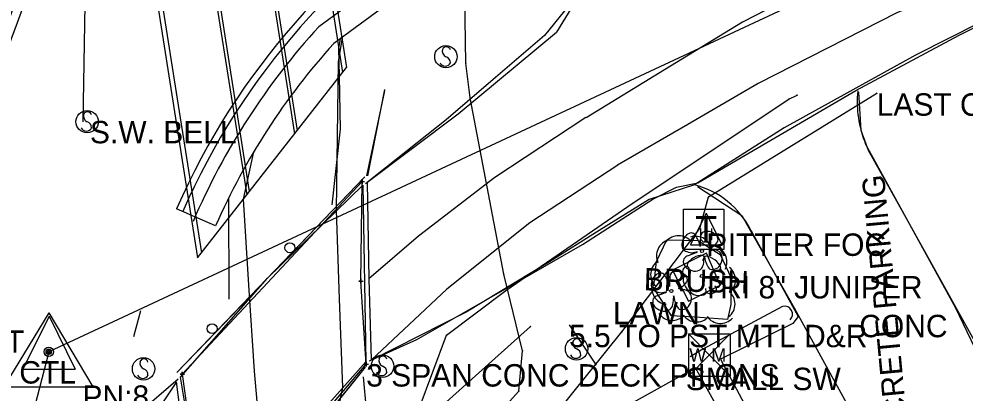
# Model space of a CAD drawing. Extents: x 978516 to 993312, y 1836504 to 1846212.
# Drawn here: x 992686.2 to 992897.2, y 1840515.9 to 1840599.3 of the extents above; entities that cross this region are included whole.
import ezdxf

# ---------------------------------------------------------------- set-up
doc = ezdxf.new("R2010")
doc.units = 0
for name, color, linetype in [('R_Drainage', 7, 'Continuous'), ('R_MOT Stage 1 Widening', 7, 'Continuous'), ('R_Proposed Road', 7, 'Continuous'), ('S_BASELINE', 7, 'Continuous'), ('S_BRIDGE', 7, 'Continuous'), ('S_BRIDGE_ANNOT', 7, 'Continuous'), ('S_BUILDING', 7, 'Continuous'), ('S_CAL_CORNER', 7, 'Continuous'), ('S_DRIVEWAY', 7, 'Continuous'), ('S_EDGE_PAVEMENT', 7, 'Continuous'), ('S_FENCE', 7, 'Continuous'), ('S_FIBER_OPTIC_CABLE', 7, 'Continuous'), ('S_FIBER_OPTIC_CABLE_ANNOT', 7, 'Continuous'), ('S_GAS_UTILITIES', 7, 'Continuous'), ('S_GUARDRAIL', 7, 'Continuous'), ('S_HEADWALL', 7, 'Continuous'), ('S_PARKING', 7, 'Continuous'), ('S_PARKING_ANNOT', 7, 'Continuous'), ('S_PAVEMENT_CROWN', 7, 'Continuous'), ('S_PRIMARY_CTL', 7, 'Continuous'), ('S_PRIMARY_CTL_ANNOT', 7, 'Continuous'), ('S_SHOULDER', 7, 'Continuous'), ('S_SIDEWALK', 7, 'Continuous'), ('S_SIGN', 7, 'Continuous'), ('S_SIGN_ANNOT', 7, 'Continuous'), ('S_STR_PT_SYM', 7, 'Continuous'), ('S_STREAM', 7, 'Continuous'), ('S_SURVEY_TEXT_ANNOT', 7, 'Continuous'), ('S_TELEPHONE_UTILITIES', 7, 'Continuous'), ('S_TREE', 7, 'Continuous'), ('S_TREE_ANNOT', 7, 'Continuous'), ('S_UNDERGROUND_CABLE', 7, 'Continuous'), ('S_UTILITY_POLE_ANNOT', 7, 'Continuous'), ('S_UTL_PT_SYM', 7, 'Continuous'), ('S_WALL', 7, 'Continuous'), ('S_WATER_UTILITIES', 7, 'Continuous')]:
    doc.layers.add(name, color=color, linetype=linetype)

msp = doc.modelspace()

# ---------------------------------------------------------------- linework, layer by layer
at = {"layer": 'R_Drainage'}
for p, q in [((992722.23, 1840823.99), (992759.26, 1840588.45)), ((992721.57, 1840821.45), (992758.38, 1840587.32)), ((992711.58, 1840807.74), (992748.27, 1840574.41)), ((992711.02, 1840806.97), (992747.7, 1840573.69)), ((992701.03, 1840793.26), (992737.59, 1840560.77)), ((992700.48, 1840792.49), (992737.03, 1840560.05)), ((992689.24, 1840780.01), (992726.03, 1840546.01)), ((992690.27, 1840780.17), (992726.91, 1840547.13)), ((992726.03, 1840546.01), (992759.26, 1840588.45))]:
    msp.add_line(p, q, dxfattribs=at)
at = {"layer": 'R_MOT Stage 1 Widening'}
for radius in [585.96, 583.96]:
    msp.add_arc((993234.41, 1840398.18), radius, 157.55254, 164.93538, dxfattribs=at)
at = {"layer": 'R_Proposed Road'}
for p, q in [((992802.25, 1840633.66), (992753.09, 1840597.56)), ((992804.81, 1840629.34), (992756.46, 1840593.83)), ((992730.1, 1840553.16), (992721.4, 1840556.97)), ((992711.86, 1840528.47), (992713.43, 1840534.3))]:
    msp.add_line(p, q, dxfattribs=at)
for radius, start, end in [(160, 86.363, 156.3203), (158.5, 86.363, 156.3203), (155.5, 137.6025, 156.741), (150.5, 137.7895, 156.3203)]:
    msp.add_arc((992867.93, 1840492.71), radius, start, end, dxfattribs=at)
at = {"layer": 'S_BASELINE'}
for p, q in [((993084.19, 1840707.66), (992692.91, 1840525.06)), ((992692.91, 1840525.06), (992469.46, 1839669.75))]:
    msp.add_line(p, q, dxfattribs=at)
at = {"layer": 'S_BRIDGE'}
for p, q in [((992762.75, 1840563.05), (992722.66, 1840520.07)), ((992762.5, 1840540.83), (992762.75, 1840563.05)), ((992763.66, 1840522.31), (992762.5, 1840540.83)), ((992727.57, 1840479.81), (992763.66, 1840522.31)), ((992722.66, 1840520.07), (992725.42, 1840500.17))]:
    msp.add_line(p, q, dxfattribs=at)
msp.add_lwpolyline([(992741.67, 1840541.48), (992762.9, 1840562.2), (992763.6, 1840522.8), (992746.71, 1840503.81), (992728.74, 1840480.59), (992722.25, 1840519.42)], close=True, dxfattribs=at)
at = {"layer": 'S_BUILDING'}
msp.add_lwpolyline([(992808.57, 1840505.65), (992829.2, 1840468.57), (992857.68, 1840484.4), (992837.04, 1840521.49)], close=True, dxfattribs=at)
at = {"layer": 'S_CAL_CORNER'}
for p, q in [((992693, 1840533.04), (992687.12, 1840521.22)), ((992693, 1840533.04), (992698.81, 1840521.22)), ((992687.12, 1840521.22), (992698.81, 1840521.22))]:
    msp.add_line(p, q, dxfattribs=at)
at = {"layer": 'S_DRIVEWAY'}
for points in [[(992906.73, 1840514.11), (992898.92, 1840528.17), (992891.11, 1840542.23), (992883.37, 1840556.1), (992875.63, 1840569.96), (992874.01, 1840574.41), (992873.47, 1840582.95)], [(992837.52, 1840561.93), (992847.36, 1840555.43), (992859.05, 1840534.9), (992865.85, 1840522.52), (992872.66, 1840510.14), (992879.81, 1840497.28)]]:
    msp.add_lwpolyline(points, dxfattribs=at)
at = {"layer": 'S_EDGE_PAVEMENT'}
for points in [[(993177.91, 1840647.47), (993161.87, 1840647.02), (993145.83, 1840646.57), (993129.79, 1840646.12), (993113.75, 1840645.67), (993089.5, 1840644.32), (993065.25, 1840642.97), (993051.93, 1840641.71), (993038.62, 1840640.45), (993025.3, 1840639.2), (993011.99, 1840637.94), (992997.08, 1840635.43), (992982.18, 1840632.93), (992964.68, 1840629), (992947.18, 1840625.07), (992929.74, 1840619.35), (992912.31, 1840613.64), (992897.13, 1840607.12), (992881.95, 1840600.61), (992866.5, 1840592.73), (992851.05, 1840584.86), (992835.38, 1840575.78), (992819.71, 1840566.7)], [(992816.12, 1840634.02), (992817.57, 1840628.43), (992818.03, 1840619.07), (992813.29, 1840609.04), (992807.87, 1840601.1), (992803.43, 1840595.57), (992792.47, 1840586.2), (992781.52, 1840576.82), (992763.89, 1840562.82), (992764.24, 1840541.31), (992764.8, 1840523.27)], [(992814.31, 1840609.86), (992806.06, 1840596.37)], [(992819.73, 1840566.69), (992800.1, 1840553.83), (992781.65, 1840539), (992764.81, 1840523.24)], [(992727.17, 1840479.58), (992723.79, 1840499.26), (992721.4, 1840518.33), (992709.95, 1840501.18), (992698.5, 1840484.04), (992688.92, 1840468.82), (992679.35, 1840453.6), (992673.45, 1840441.41), (992667.56, 1840429.21), (992661.66, 1840417.01)]]:
    msp.add_lwpolyline(points, dxfattribs=at)
at = {"layer": 'S_FENCE'}
msp.add_lwpolyline([(992690.72, 1840637.87), (992701.52, 1840637.54), (992700.49, 1840576.34)], dxfattribs=at)
at = {"layer": 'S_FIBER_OPTIC_CABLE'}
for p, q in [((992785.88, 1840589.39), (992784.86, 1840660.38)), ((992786.81, 1840581.67), (992785.88, 1840589.39)), ((992839.93, 1840559.6), (992877.46, 1840582.7)), ((992794.32, 1840542.4), (992786.81, 1840581.67)), ((992838.05, 1840552.56), (992839.93, 1840559.6)), ((992820.65, 1840529.49), (992838.05, 1840552.56)), ((992798.51, 1840525.29), (992794.32, 1840542.4)), ((992788.25, 1840489.33), (992820.65, 1840529.49)), ((992797.72, 1840516.31), (992798.51, 1840525.29)), ((992781.05, 1840497.97), (992797.72, 1840516.31))]:
    msp.add_line(p, q, dxfattribs=at)
at = {"layer": 'S_GAS_UTILITIES'}
for p, q in [((992857.87, 1840581.4), (992859.74, 1840582.32)), ((992823.2, 1840558.29), (992857.87, 1840581.4)), ((992794.82, 1840538.73), (992823.2, 1840558.29)), ((992781.54, 1840528.78), (992794.82, 1840538.73)), ((992780.08, 1840512.54), (992800.28, 1840530.72)), ((992775.47, 1840512.42), (992781.54, 1840528.78))]:
    msp.add_line(p, q, dxfattribs=at)
at = {"layer": 'S_GUARDRAIL'}
for points in [[(992721.45, 1840520.43), (992763.34, 1840564.05)], [(992756.09, 1840556.5), (992763.34, 1840564.05)], [(992747.43, 1840547.48), (992756.09, 1840556.5)], [(992730.11, 1840529.45), (992747.43, 1840547.48)], [(992721.45, 1840520.43), (992730.11, 1840529.45)], [(992763.45, 1840521.65), (992727.06, 1840476.56)], [(992763.45, 1840521.65), (992755.6, 1840511.92)]]:
    msp.add_lwpolyline(points, dxfattribs=at)
for centre in [(992746.64, 1840548.25), (992729.32, 1840530.21)]:
    msp.add_circle(centre, 1.1, dxfattribs=at)
at = {"layer": 'S_HEADWALL'}
for points in [[(992767.77, 1840583.55), (992763.94, 1840564.3)], [(992763, 1840519.48), (992763.68, 1840512.17)]]:
    msp.add_lwpolyline(points, dxfattribs=at)
at = {"layer": 'S_PARKING'}
for points in [[(992874.99, 1840571.38), (992895.05, 1840534.87), (992906.92, 1840510.07)], [(992849.37, 1840552.22), (992859.98, 1840532.9), (992858.79, 1840531.37), (992842.62, 1840523.39), (992861.57, 1840487.89), (992878.33, 1840497.58)]]:
    msp.add_lwpolyline(points, dxfattribs=at)
msp.add_arc((992898.2, 1840580.9), 25.09, 174.5543, 202.3004, dxfattribs=at)
msp.add_ellipse((992831.99, 1840543.4), major_axis=(5.73, 18.65), ratio=0.998187, start_param=5.479068, end_param=6.328259, dxfattribs=at)
at = {"layer": 'S_PAVEMENT_CROWN'}
for points in [[(992907.52, 1840626.08), (992890.94, 1840619.3), (992874.36, 1840612.52), (992860.96, 1840605.55), (992847.56, 1840598.59), (992830.13, 1840587.9), (992812.7, 1840577.21)], [(992812.6, 1840577.29), (992792.33, 1840563.91), (992775.35, 1840550.83), (992764.23, 1840541.36)]]:
    msp.add_lwpolyline(points, dxfattribs=at)
at = {"layer": 'S_PRIMARY_CTL'}
for p, q in [((992692.91, 1840533.76), (992682.88, 1840517.25)), ((992692.91, 1840533.76), (992702.74, 1840517.25)), ((992682.88, 1840517.25), (992702.74, 1840517.25))]:
    msp.add_line(p, q, dxfattribs=at)
for radius in [1.04, 0.609, 0.344]:
    msp.add_circle((992692.91, 1840525.06), radius, dxfattribs=at)
at = {"layer": 'S_SHOULDER'}
for points in [[(992764.42, 1840523.04), (992774.98, 1840527.84), (992792.1, 1840537.6), (992811.9, 1840549), (992827.56, 1840559.12), (992832.85, 1840561.75), (992837.56, 1840562.73), (992872.77, 1840583.33), (992895.85, 1840595.64), (992918.17, 1840606.95), (992952.31, 1840617.76), (992986.76, 1840625.23), (993023.98, 1840630.67)], [(992900.35, 1840598.41), (992886.07, 1840591.18), (992871.44, 1840583.1), (992856.81, 1840575.03), (992836.84, 1840562.32), (992826.74, 1840559.04), (992815.62, 1840552.1), (992804.51, 1840545.15), (992785.95, 1840533.87), (992764.82, 1840523.23)], [(992763.48, 1840562.59), (992784.18, 1840578.13), (992806.06, 1840596.37)], [(992679.93, 1840469.45), (992694.86, 1840491.14), (992712.59, 1840511.13), (992721.74, 1840519.04)]]:
    msp.add_lwpolyline(points, dxfattribs=at)
at = {"layer": 'S_SIDEWALK'}
msp.add_lwpolyline([(992856.48, 1840535.18), (992838.73, 1840525.65), (992835.85, 1840523.95)], dxfattribs=at)
msp.add_arc((992856.92, 1840533.45), 1.78, 313.4272, 104.1775, dxfattribs=at)
at = {"layer": 'S_SIGN'}
msp.add_line((992808.88, 1840531.09), (992814.94, 1840522.06), dxfattribs=at)
for centre in [(992781.43, 1840590.87), (992701.45, 1840576.37), (992810.54, 1840525.71), (992714.03, 1840521.25), (992767.3, 1840521.85)]:
    msp.add_circle(centre, 2.49, dxfattribs=at)
for centre, radius, start, end in [((992782.12, 1840592.19), 1.5, 167.1196, 241.9813), ((992781.51, 1840592.13), 0.95, 16.5258, 156.8957), ((992781.02, 1840589.52), 1.4, 358.6529, 73.7063), ((992781.28, 1840590.04), 1.28, 204.641, 335.359), ((992702.13, 1840577.69), 1.5, 167.1196, 241.9813), ((992701.52, 1840577.64), 0.95, 16.5258, 156.8957), ((992701.04, 1840575.03), 1.4, 358.6529, 73.7063), ((992701.29, 1840575.55), 1.28, 204.641, 335.359), ((992811.22, 1840527.04), 1.5, 167.1196, 241.9813), ((992810.61, 1840526.98), 0.95, 16.5258, 156.8957), ((992810.13, 1840524.37), 1.4, 358.6529, 73.7063), ((992714.72, 1840522.57), 1.5, 167.1196, 241.9813), ((992714.11, 1840522.51), 0.95, 16.5258, 156.8957), ((992767.98, 1840523.18), 1.5, 167.1196, 241.9813), ((992767.37, 1840523.12), 0.95, 16.5258, 156.8957), ((992810.38, 1840524.89), 1.28, 204.641, 335.359), ((992713.62, 1840519.9), 1.4, 358.6529, 73.7063), ((992766.88, 1840520.51), 1.4, 358.6529, 73.7063), ((992713.88, 1840520.42), 1.28, 204.641, 335.359), ((992767.14, 1840521.03), 1.28, 204.641, 335.359)]:
    msp.add_arc(centre, radius, start, end, dxfattribs=at)
at = {"layer": 'S_STR_PT_SYM'}
for points in [[(992762.75, 1840563.05), (992762.75, 1840563.55), (992762.75, 1840563.05), (992762.25, 1840563.05), (992762.75, 1840563.05), (992762.75, 1840562.55), (992762.75, 1840563.05), (992763.25, 1840563.05)], [(992762.5, 1840540.83), (992762.5, 1840541.33), (992762.5, 1840540.83), (992762, 1840540.83), (992762.5, 1840540.83), (992762.5, 1840540.33), (992762.5, 1840540.83), (992763, 1840540.83)], [(992763.66, 1840522.31), (992763.66, 1840522.81), (992763.66, 1840522.31), (992763.16, 1840522.31), (992763.66, 1840522.31), (992763.66, 1840521.81), (992763.66, 1840522.31), (992764.16, 1840522.31)], [(992722.66, 1840520.07), (992722.66, 1840520.57), (992722.66, 1840520.07), (992722.16, 1840520.07), (992722.66, 1840520.07), (992722.66, 1840519.57), (992722.66, 1840520.07), (992723.16, 1840520.07)]]:
    msp.add_lwpolyline(points, dxfattribs=at)
at = {"layer": 'S_STREAM'}
for points in [[(992758.28, 1840595.17), (992757.44, 1840589.73), (992757.19, 1840573.18), (992756.93, 1840556.62), (992757.65, 1840536.86), (992758.37, 1840517.1), (992755.48, 1840503.1), (992752.59, 1840489.1), (992750.17, 1840482.23), (992751.22, 1840469.43), (992752.27, 1840456.64), (992752.39, 1840435.4), (992746.88, 1840418.83), (992741.38, 1840402.27), (992735.04, 1840383.73), (992728.7, 1840365.18)], [(992757.89, 1840594.88), (992757.49, 1840592.74), (992757.65, 1840586.53), (992757.87, 1840574.71), (992755.97, 1840557.84)], [(992738.56, 1840569.62), (992736.23, 1840559.11), (992737.44, 1840539.91), (992738.66, 1840520.72), (992739.87, 1840507.19), (992741.09, 1840493.67), (992741.97, 1840482.66), (992743.33, 1840457.87), (992744.81, 1840435.72), (992739.02, 1840420.42), (992733.23, 1840405.13), (992725.57, 1840391.67), (992717.91, 1840378.21)], [(992733.08, 1840536.77), (992733.01, 1840559.39)]]:
    msp.add_lwpolyline(points, dxfattribs=at)
at = {"layer": 'S_TELEPHONE_UTILITIES'}
msp.add_lwpolyline([(992834.41, 1840547.87), (992834.41, 1840556.87), (992843.41, 1840556.87), (992843.41, 1840547.87)], close=True, dxfattribs=at)
at = {"layer": 'S_TREE'}
for p, q in [((992838.14, 1840548.53), (992837.89, 1840549.42)), ((992840.09, 1840548.07), (992840.47, 1840548.23)), ((992837.49, 1840547.37), (992836.52, 1840547.15)), ((992839.03, 1840546.2), (992838.65, 1840545.35)), ((992839.02, 1840546.44), (992839.1, 1840546)), ((992835.24, 1840544.19), (992835.74, 1840543.6)), ((992842.6, 1840543.41), (992841.94, 1840543.14)), ((992831.31, 1840539.61), (992831.07, 1840540.5)), ((992834.58, 1840541.86), (992835.7, 1840541.86)), ((992830.66, 1840538.45), (992829.69, 1840538.23)), ((992833.26, 1840539.15), (992833.64, 1840539.31)), ((992835.74, 1840538.68), (992836.21, 1840539.38)), ((992839.42, 1840538.41), (992839.34, 1840539.19)), ((992841.82, 1840539.3), (992841.36, 1840539.73)), ((992832.2, 1840537.52), (992832.27, 1840537.08))]:
    msp.add_line(p, q, dxfattribs=at)
msp.add_lwpolyline([(992827.77, 1840539.78), (992828.35, 1840545.19), (992830.68, 1840550.01), (992837.69, 1840549.9), (992842.56, 1840546.73), (992845, 1840541.56), (992844.97, 1840535.61), (992844.18, 1840532.27), (992838.01, 1840532.68), (992831.72, 1840533.07), (992827.58, 1840539.63)], dxfattribs=at)
for centre in [(992838.51, 1840547.55), (992838.48, 1840541.96), (992831.68, 1840538.63)]:
    msp.add_circle(centre, 0.341, dxfattribs=at)
for centre, start, end in [((992833.28, 1840547.31), 38.3201, 139.917), ((992837.05, 1840547.19), 6.1486, 107.7455), ((992831.99, 1840546.44), 103.3418, 204.9387), ((992840.43, 1840545.09), 334.4746, 76.0716), ((992830.71, 1840542.3), 123.0699, 224.6669), ((992842.34, 1840541.07), 308.8713, 50.4682), ((992830.95, 1840539.27), 161.4611, 263.058), ((992842.23, 1840535.74), 308.8713, 50.4682), ((992831.88, 1840535.7), 215.6654, 317.2623), ((992837.31, 1840535.36), 215.6654, 317.2623), ((992842.62, 1840535.04), 215.392, 316.9889)]:
    msp.add_arc(centre, 3.64, start, end, dxfattribs=at)
for centre, major_axis, ratio, start_param, end_param in [((992835.62, 1840549.57), (-1.03, -1.88), 0.662338, 3.141593, 6.283185), ((992837.27, 1840550.44), (0.62, -1.01), 0.083512, 0, 3.141593), ((992838.21, 1840549.86), (-0.07, -1.33), 0.068203, 3.141593, 6.283185), ((992840.17, 1840550.44), (1.89, -0.74), 0.673998, 0, 3.141593), ((992841.26, 1840548.96), (-0.798, -0.73), 0.092159, 0, 3.141593), ((992834.94, 1840546.15), (0.477, 0.328), 0.136309, 0, 3.141593), ((992835.55, 1840547.42), (0.964, -0.267), 0.113563, 3.141593, 6.283185), ((992837.14, 1840545.16), (1.86, 1.08), 0.471018, 0, 3.141593), ((992836.45, 1840546.92), (1.04, 0.44), 0.002756, 3.141593, 6.283185), ((992838.79, 1840545.27), (0.19, 1.31), 0.114148, 3.141593, 5.822668), ((992840.79, 1840544.83), (-1.81, 1.36), 0.405113, 3.141593, 6.283186), ((992841.05, 1840547.84), (0.96, -0.23), 0.056001, 0, 3.141593), ((992841.12, 1840545.56), (0.88, 2.05), 0.81717, 3.141593, 6.283185), ((992836.53, 1840544.89), (2.07, -0.93), 0.760068, 3.141593, 6.283185), ((992834.91, 1840543.04), (0.31, 1.03), 0.646762, 0, 3.141593), ((992839.36, 1840545.23), (0.254, -0.771), 0.051603, 3.141593, 6.283185), ((992839.93, 1840543.99), (-0.321, 0.467), 0.094289, 0, 3.141593), ((992828.79, 1840540.65), (-1.03, -1.88), 0.662338, 3.141593, 6.283185), ((992830.44, 1840541.52), (0.62, -1.01), 0.083512, 0, 3.141593), ((992831.38, 1840540.94), (-0.07, -1.33), 0.068203, 3.141593, 6.283185), ((992833.34, 1840541.52), (1.89, -0.74), 0.673998, 0, 3.141593), ((992835.21, 1840540.39), (-0.61, 1.6), 0.420543, 6.283185, 9.424777), ((992842.15, 1840541.43), (0.46, 2.04), 0.482994, 3.141593, 6.283185), ((992834.44, 1840540.04), (-0.798, -0.73), 0.092159, 0, 3.141593), ((992828.72, 1840538.5), (0.964, -0.267), 0.113563, 3.141593, 6.283185), ((992829.62, 1840538), (1.04, 0.44), 0.002756, 3.141593, 6.283185), ((992834.22, 1840538.92), (0.96, -0.23), 0.056001, 0, 3.141593), ((992834.3, 1840536.64), (0.88, 2.05), 0.81717, 3.141593, 6.283185), ((992837.67, 1840538.61), (-1.83, 0.19), 0.529943, 0, 3.141593), ((992840.63, 1840538.9), (1.09, 0.46), 0.711534, 3.141592, 6.283185), ((992829.7, 1840535.97), (2.07, -0.93), 0.760068, 3.141593, 6.283185), ((992828.11, 1840537.23), (0.477, 0.328), 0.136309, 0, 3.141593), ((992831.96, 1840536.35), (0.19, 1.31), 0.114148, 3.141593, 5.822668), ((992832.53, 1840536.31), (0.254, -0.771), 0.051603, 3.141593, 6.283185), ((992833.1, 1840535.07), (-0.321, 0.467), 0.094289, 0, 3.141593)]:
    msp.add_ellipse(centre, major_axis=major_axis, ratio=ratio, start_param=start_param, end_param=end_param, dxfattribs=at)
at = {"layer": 'S_UNDERGROUND_CABLE'}
for p, q in [((992839.44, 1840555.99), (992835.92, 1840548.89)), ((992839.44, 1840555.99), (992842.93, 1840548.89)), ((992838.24, 1840550.13), (992838.24, 1840552.58)), ((992840.6, 1840552.58), (992840.6, 1840550.13)), ((992835.92, 1840548.89), (992842.93, 1840548.89)), ((992838.86, 1840549.48), (992838.24, 1840550.13)), ((992840.06, 1840549.48), (992838.86, 1840549.48)), ((992840.6, 1840550.13), (992840.06, 1840549.48))]:
    msp.add_line(p, q, dxfattribs=at)
at = {"layer": 'S_UTL_PT_SYM'}
for points in [[(992785.88, 1840589.39), (992785.88, 1840589.44), (992785.88, 1840589.39), (992785.83, 1840589.39), (992785.88, 1840589.39), (992785.88, 1840589.34), (992785.88, 1840589.39), (992785.93, 1840589.39)], [(992859.74, 1840582.32), (992859.74, 1840582.37), (992859.74, 1840582.32), (992859.69, 1840582.32), (992859.74, 1840582.32), (992859.74, 1840582.27), (992859.74, 1840582.32), (992859.79, 1840582.32)], [(992877.46, 1840582.7), (992877.46, 1840582.75), (992877.46, 1840582.7), (992877.41, 1840582.7), (992877.46, 1840582.7), (992877.46, 1840582.65), (992877.46, 1840582.7), (992877.51, 1840582.7)], [(992786.81, 1840581.67), (992786.81, 1840581.72), (992786.81, 1840581.67), (992786.76, 1840581.67), (992786.81, 1840581.67), (992786.81, 1840581.62), (992786.81, 1840581.67), (992786.86, 1840581.67)], [(992857.87, 1840581.4), (992857.87, 1840581.45), (992857.87, 1840581.4), (992857.82, 1840581.4), (992857.87, 1840581.4), (992857.87, 1840581.35), (992857.87, 1840581.4), (992857.92, 1840581.4)], [(992839.93, 1840559.6), (992839.93, 1840559.65), (992839.93, 1840559.6), (992839.88, 1840559.6), (992839.93, 1840559.6), (992839.93, 1840559.55), (992839.93, 1840559.6), (992839.98, 1840559.6)], [(992823.2, 1840558.29), (992823.2, 1840558.34), (992823.2, 1840558.29), (992823.15, 1840558.29), (992823.2, 1840558.29), (992823.2, 1840558.24), (992823.2, 1840558.29), (992823.25, 1840558.29)], [(992838.05, 1840552.56), (992838.05, 1840552.61), (992838.05, 1840552.56), (992838, 1840552.56), (992838.05, 1840552.56), (992838.05, 1840552.51), (992838.05, 1840552.56), (992838.1, 1840552.56)], [(992794.32, 1840542.4), (992794.32, 1840542.45), (992794.32, 1840542.4), (992794.27, 1840542.4), (992794.32, 1840542.4), (992794.32, 1840542.35), (992794.32, 1840542.4), (992794.37, 1840542.4)], [(992794.82, 1840538.73), (992794.82, 1840538.78), (992794.82, 1840538.73), (992794.77, 1840538.73), (992794.82, 1840538.73), (992794.82, 1840538.68), (992794.82, 1840538.73), (992794.87, 1840538.73)], [(992800.28, 1840530.72), (992800.28, 1840530.77), (992800.28, 1840530.72), (992800.23, 1840530.72), (992800.28, 1840530.72), (992800.28, 1840530.67), (992800.28, 1840530.72), (992800.33, 1840530.72)], [(992820.65, 1840529.49), (992820.65, 1840529.54), (992820.65, 1840529.49), (992820.6, 1840529.49), (992820.65, 1840529.49), (992820.65, 1840529.44), (992820.65, 1840529.49), (992820.7, 1840529.49)], [(992781.54, 1840528.78), (992781.54, 1840528.83), (992781.54, 1840528.78), (992781.49, 1840528.78), (992781.54, 1840528.78), (992781.54, 1840528.73), (992781.54, 1840528.78), (992781.59, 1840528.78)], [(992798.51, 1840525.29), (992798.51, 1840525.34), (992798.51, 1840525.29), (992798.46, 1840525.29), (992798.51, 1840525.29), (992798.51, 1840525.24), (992798.51, 1840525.29), (992798.56, 1840525.29)], [(992797.72, 1840516.31), (992797.72, 1840516.36), (992797.72, 1840516.31), (992797.67, 1840516.31), (992797.72, 1840516.31), (992797.72, 1840516.26), (992797.72, 1840516.31), (992797.77, 1840516.31)]]:
    msp.add_lwpolyline(points, dxfattribs=at)
at = {"layer": 'S_WALL'}
msp.add_lwpolyline([(992767.77, 1840583.28), (992763.76, 1840564.32)], dxfattribs=at)
msp.add_lwpolyline([(992839.53, 1840547.03), (992831.97, 1840543.25), (992835.51, 1840536.33), (992842.57, 1840539.95)], close=True, dxfattribs=at)
at = {"layer": 'S_WATER_UTILITIES'}
for p, q in [((992835.48, 1840529.1), (992844.82, 1840529.1)), ((992835.48, 1840529.1), (992835.48, 1840519.6)), ((992835.48, 1840529.1), (992844.82, 1840519.6)), ((992844.82, 1840529.1), (992835.48, 1840519.6)), ((992844.82, 1840529.1), (992844.82, 1840519.6)), ((992835.48, 1840519.6), (992844.82, 1840519.6))]:
    msp.add_line(p, q, dxfattribs=at)

# ---------------------------------------------------------------- texts
at = {"layer": 'S_BRIDGE_ANNOT'}
msp.add_text('3 SPAN CONC DECK PILONS', height=5, dxfattribs=at).set_placement((992763.66, 1840517.31))
at = {"layer": 'S_FIBER_OPTIC_CABLE_ANNOT'}
msp.add_text('LAST OF MARKINGS', height=5, dxfattribs=at).set_placement((992877.46, 1840577.7))
at = {"layer": 'S_PARKING_ANNOT'}
msp.add_text('CONCRETE PARKING', height=5.0005, rotation=95.3107, dxfattribs=at).set_placement((992885.53, 1840495.57))
at = {"layer": 'S_PRIMARY_CTL'}
msp.add_text('CTL', height=5, dxfattribs=at).set_placement((992686.33, 1840517.98))
at = {"layer": 'S_PRIMARY_CTL_ANNOT'}
msp.add_text('PN:8', height=5, dxfattribs=at).set_placement((992700.41, 1840512.56))
at = {"layer": 'S_SIGN_ANNOT'}
msp.add_text('5.5 TO PST MTL D&R', height=5, dxfattribs=at).set_placement((992808.88, 1840526.09))
at = {"layer": 'S_SURVEY_TEXT_ANNOT'}
for s, p in [('LAWN', (992818.67, 1840531.2)), ('CONC', (992873.57, 1840528.31)), ('ASPHALT', (992656.97, 1840524.84)), ('SMALL SW', (992834.89, 1840516.51))]:
    msp.add_text(s, height=5, dxfattribs=at).set_placement(p)
at = {"layer": 'S_TELEPHONE_UTILITIES'}
msp.add_text('T', height=6, dxfattribs=at).set_placement((992836.97, 1840549.37))
at = {"layer": 'S_TREE_ANNOT'}
msp.add_text('BRUSH', height=5, rotation=358.2942, dxfattribs=at).set_placement((992825.48, 1840538.77))
msp.add_text('TRI 8" JUNIPER', height=5, dxfattribs=at).set_placement((992838.48, 1840536.96))
at = {"layer": 'S_UTILITY_POLE_ANNOT'}
for s, p in [('S.W. BELL', (992702.08, 1840571.55)), ('RITTER FOC', (992839.44, 1840546.45))]:
    msp.add_text(s, height=5, dxfattribs=at).set_placement(p)
at = {"layer": 'S_WATER_UTILITIES'}
msp.add_text('W M', height=3, dxfattribs=at).set_placement((992835.68, 1840522.86))

doc.saveas('drawing.dxf')
